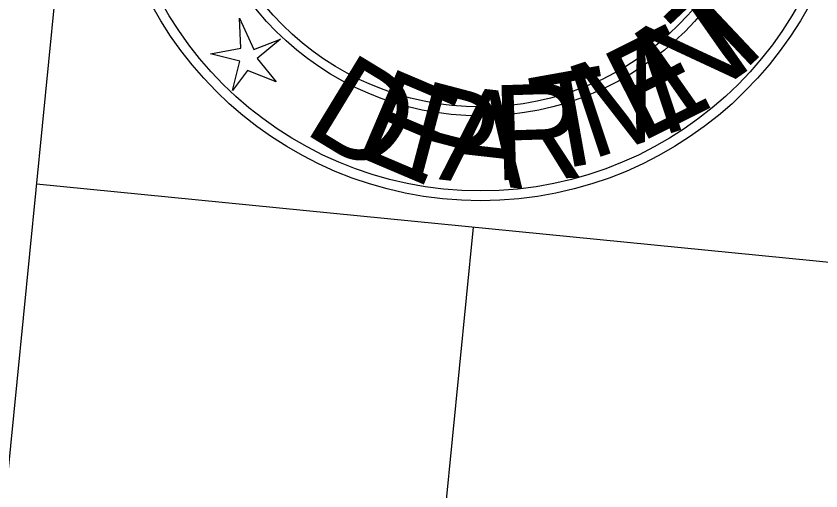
# Model space of a CAD drawing. Extents: x 1796928 to 1798191, y 245238 to 247038.
# Drawn here: x 1798036.13 to 1798085.62, y 246124.79 to 246154.02 of the extents above; entities that cross this region are included whole.
import ezdxf

# ---------------------------------------------------------------- set-up
doc = ezdxf.new("R2010")
doc.units = 0
for name, color, linetype in [('great seal', 7, 'Continuous'), ('SHT-BDR', 7, 'Continuous'), ('SHT-BNDRY', 7, 'Continuous')]:
    doc.layers.add(name, color=color, linetype=linetype)

msp = doc.modelspace()

# ---------------------------------------------------------------- linework, layer by layer
at = {"layer": 'great seal'}
msp.add_lwpolyline([(1798048.075, 246151.692), (1798049.957, 246152.034), (1798049.877, 246153.89), (1798050.742, 246151.956), (1798052.388, 246152.586), (1798050.951, 246151.407), (1798052.13, 246149.971), (1798050.351, 246150.675), (1798049.437, 246149.445), (1798049.88, 246151.249)], close=True, dxfattribs=at)
msp.add_lwpolyline([(1798048.075, 246151.692), (1798049.957, 246152.034), (1798049.877, 246153.89), (1798050.742, 246151.956), (1798052.388, 246152.586), (1798050.951, 246151.407), (1798052.13, 246149.971), (1798050.351, 246150.675), (1798049.437, 246149.445), (1798049.88, 246151.249)], close=True, dxfattribs=at)
msp.add_lwpolyline([(1798048.075, 246151.692), (1798049.957, 246152.034), (1798049.877, 246153.89), (1798050.742, 246151.956), (1798052.388, 246152.586), (1798050.951, 246151.407), (1798052.13, 246149.971), (1798050.351, 246150.675), (1798049.437, 246149.445), (1798049.88, 246151.249)], close=True, dxfattribs=at)
for radius in [22.994, 22.994, 22.994, 22.389, 22.389, 22.389, 17.779, 17.779, 17.779, 17.222, 17.222, 17.222]:
    msp.add_circle((1798064.692, 246165.645), radius, dxfattribs=at)
at = {"layer": 'SHT-BDR'}
msp.add_lwpolyline([(1797960.77, 245369.322), (1798108.469, 246862.035), (1797163.084, 246955.579), (1797015.384, 245462.865)], close=True, dxfattribs=at)
at = {"layer": 'SHT-BNDRY'}
for p, q in [((1798087.197, 246138.751), (1798037.39, 246143.679)), ((1797987.638, 245366.663), (1798064.259, 246141.021))]:
    msp.add_line(p, q, dxfattribs=at)

# ---------------------------------------------------------------- texts
at = {"layer": 'great seal'}
for s, rotation, p in [('T', 43.2798, (1798079.819, 246149.607)), ('T', 43.2798, (1798079.819, 246149.607)), ('T', 43.2798, (1798079.819, 246149.607)), ('N', 34.9914, (1798076.997, 246147.774)), ('N', 34.9914, (1798076.997, 246147.774)), ('N', 34.9914, (1798076.997, 246147.774)), ('E', 26.703, (1798074.462, 246146.177)), ('E', 26.703, (1798074.462, 246146.177)), ('E', 26.703, (1798074.462, 246146.177)), ('M', 18.4147, (1798071.456, 246145.154)), ('M', 18.4147, (1798071.456, 246145.154)), ('M', 18.4147, (1798071.456, 246145.154)), ('D', 328.6843, (1798053.675, 246146.913)), ('D', 328.6843, (1798053.675, 246146.913)), ('D', 328.6843, (1798053.675, 246146.913)), ('E', 336.9727, (1798056.71, 246145.557)), ('E', 336.9727, (1798056.71, 246145.557)), ('E', 336.9727, (1798056.71, 246145.557)), ('T', 10.1263, (1798068.477, 246144.392)), ('T', 10.1263, (1798068.477, 246144.392)), ('T', 10.1263, (1798068.477, 246144.392)), ('P', 345.2611, (1798059.77, 246144.462)), ('P', 345.2611, (1798059.77, 246144.462)), ('P', 345.2611, (1798059.77, 246144.462)), ('R', 1.8379, (1798065.523, 246143.893)), ('R', 1.8379, (1798065.523, 246143.893)), ('R', 1.8379, (1798065.523, 246143.893)), ('A', 353.5495, (1798062.097, 246143.967)), ('A', 353.5495, (1798062.097, 246143.967)), ('A', 353.5495, (1798062.097, 246143.967))]:
    msp.add_text(s, height=5.851, rotation=rotation, dxfattribs=at).set_placement(p)

doc.saveas('drawing.dxf')
